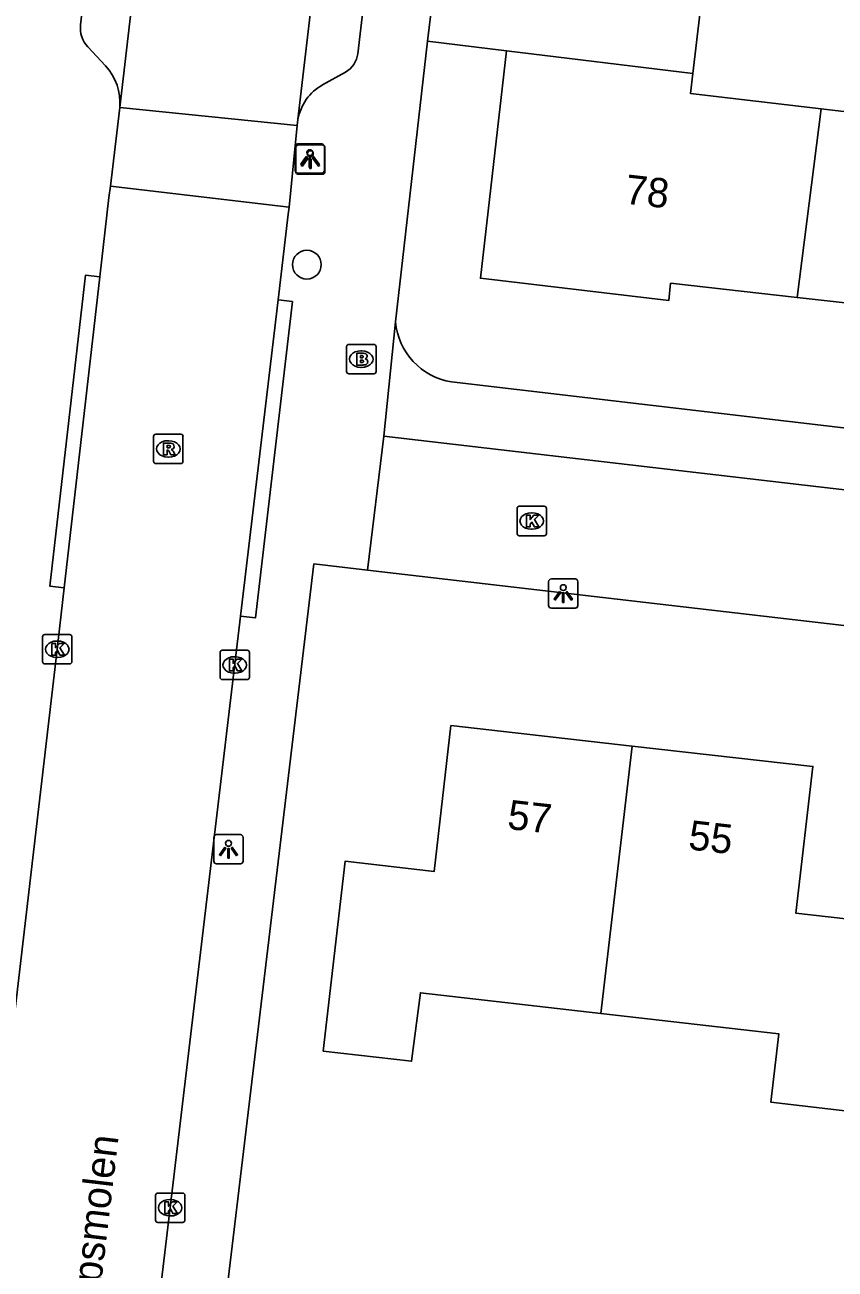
# Model space of a CAD drawing. Extents: x 161243 to 161752, y 384138 to 384885.
# Drawn here: x 161379.47 to 161407.09, y 384327.01 to 384369.39 of the extents above; entities that cross this region are included whole.
import ezdxf

# ---------------------------------------------------------------- set-up
doc = ezdxf.new("R2010")
doc.units = 0
for name, color, linetype in [('IMGEO_Boom', 7, 'Continuous'), ('IMGEO_Brandkraan', 7, 'Continuous'), ('IMGEO_Kolk', 7, 'Continuous'), ('IMGEO_Lichtpunt', 7, 'Continuous'), ('IMGEO_Openbare_ruimte_label', 7, 'Continuous'), ('IMGEO_Pand', 7, 'Continuous'), ('IMGEO_Pand_nummerreeks', 7, 'Continuous'), ('IMGEO_Rijbaan_lokaal_open', 7, 'Continuous'), ('IMGEO_Rioolput', 7, 'Continuous'), ('IMGEO_Voetpad_open', 7, 'Continuous')]:
    doc.layers.add(name, color=color, linetype=linetype)

msp = doc.modelspace()

# ---------------------------------------------------------------- linework, layer by layer
at = {"layer": 'IMGEO_Boom'}
msp.add_circle((161389.083, 384361.226), 0.489, dxfattribs=at)
at = {"layer": 'IMGEO_Brandkraan'}
for p, q in [((161390.438, 384357.582), (161390.438, 384358.434)), ((161390.513, 384358.508), (161391.365, 384358.508)), ((161390.926, 384358.288), (161390.951, 384358.288)), ((161391.439, 384358.434), (161391.439, 384357.582)), ((161391.365, 384357.508), (161390.513, 384357.508)), ((161390.949, 384357.728), (161390.924, 384357.728))]:
    msp.add_line(p, q, dxfattribs=at)
for points in [[(161390.438, 384357.582), (161390.438, 384358.434)], [(161390.513, 384358.508), (161391.365, 384358.508)], [(161390.786, 384358.208), (161390.786, 384357.808), (161390.999, 384357.808)], [(161391.017, 384358.208), (161390.786, 384358.208)], [(161391.439, 384358.434), (161391.439, 384357.582)], [(161390.965, 384358.127), (161390.911, 384358.127), (161390.911, 384358.051)], [(161390.911, 384358.051), (161390.964, 384358.051)], [(161390.973, 384357.975), (161390.911, 384357.975), (161390.911, 384357.894)], [(161390.911, 384357.894), (161390.973, 384357.894)], [(161391.365, 384357.508), (161390.513, 384357.508)]]:
    msp.add_lwpolyline(points, dxfattribs=at)
for centre, radius, start, end in [((161390.515, 384358.432), 0.0765, 91.552, 178.448), ((161390.515, 384358.432), 0.0765, 91.552, 178.448), ((161391.021, 384358.063), 0.145, 59.4692, 91.5367), ((161391.363, 384358.432), 0.0765, 1.552, 88.448), ((161391.363, 384358.432), 0.0765, 1.552, 88.448), ((161390.966, 384358.089), 0.0379, 267.8285, 90.9355), ((161390.974, 384357.934), 0.0404, 269.8759, 90.5077), ((161391.005, 384358.059), 0.251, 268.6676, 293.5347), ((161391.046, 384358.11), 0.0922, 285.5137, 58.1501), ((161391.051, 384357.918), 0.105, 301.3115, 78.989), ((161390.515, 384357.584), 0.0765, 181.552, 268.448), ((161390.515, 384357.584), 0.0765, 181.552, 268.448), ((161391.363, 384357.584), 0.0765, 271.552, 358.448), ((161391.363, 384357.584), 0.0765, 271.552, 358.448)]:
    msp.add_arc(centre, radius, start, end, dxfattribs=at)
for centre, major_axis, ratio, start_param, end_param in [((161390.925, 384358.008), (-0.387, 0.002), 0.722429, 4.712389, 7.853982), ((161390.95, 384358.008), (-0.39, 0.002), 0.717154, 1.570796, 4.712389)]:
    msp.add_ellipse(centre, major_axis=major_axis, ratio=ratio, start_param=start_param, end_param=end_param, dxfattribs=at)
at = {"layer": 'IMGEO_Kolk'}
for p, q in [((161396.245, 384352.069), (161396.245, 384352.921)), ((161396.32, 384352.995), (161397.172, 384352.995)), ((161396.733, 384352.775), (161396.758, 384352.775)), ((161397.246, 384352.921), (161397.246, 384352.069)), ((161397.172, 384351.995), (161396.32, 384351.995)), ((161396.756, 384352.215), (161396.731, 384352.215)), ((161380.075, 384347.701), (161380.075, 384348.553)), ((161380.15, 384348.627), (161381.002, 384348.627)), ((161381.076, 384348.553), (161381.076, 384347.701)), ((161380.563, 384348.407), (161380.588, 384348.407)), ((161386.198, 384348.092), (161387.05, 384348.092)), ((161381.002, 384347.627), (161380.15, 384347.627)), ((161380.586, 384347.847), (161380.561, 384347.847)), ((161386.123, 384347.166), (161386.123, 384348.018)), ((161386.611, 384347.872), (161386.636, 384347.872)), ((161387.124, 384348.018), (161387.124, 384347.166)), ((161386.634, 384347.312), (161386.609, 384347.312)), ((161387.05, 384347.092), (161386.198, 384347.092)), ((161383.924, 384328.677), (161383.924, 384329.529)), ((161383.999, 384329.603), (161384.851, 384329.603)), ((161384.925, 384329.529), (161384.925, 384328.677)), ((161384.412, 384329.383), (161384.437, 384329.383)), ((161384.851, 384328.603), (161383.999, 384328.603)), ((161384.435, 384328.823), (161384.41, 384328.823))]:
    msp.add_line(p, q, dxfattribs=at)
for points in [[(161396.245, 384352.069), (161396.245, 384352.921)], [(161396.32, 384352.995), (161397.172, 384352.995)], [(161397.246, 384352.921), (161397.246, 384352.069)], [(161396.566, 384352.695), (161396.689, 384352.695), (161396.689, 384352.544), (161396.819, 384352.695), (161396.983, 384352.695), (161396.837, 384352.544), (161396.99, 384352.295), (161396.838, 384352.295), (161396.753, 384352.459), (161396.689, 384352.392), (161396.689, 384352.295), (161396.566, 384352.295), (161396.566, 384352.695)], [(161397.172, 384351.995), (161396.32, 384351.995)], [(161380.075, 384347.701), (161380.075, 384348.553)], [(161380.15, 384348.627), (161381.002, 384348.627)], [(161381.076, 384348.553), (161381.076, 384347.701)], [(161380.396, 384348.327), (161380.519, 384348.327), (161380.519, 384348.176), (161380.649, 384348.327), (161380.813, 384348.327), (161380.667, 384348.176), (161380.82, 384347.927), (161380.668, 384347.927), (161380.583, 384348.091), (161380.519, 384348.024), (161380.519, 384347.927), (161380.396, 384347.927), (161380.396, 384348.327)], [(161386.198, 384348.092), (161387.05, 384348.092)], [(161381.002, 384347.627), (161380.15, 384347.627)], [(161386.123, 384347.166), (161386.123, 384348.018)], [(161386.444, 384347.792), (161386.567, 384347.792), (161386.567, 384347.641), (161386.697, 384347.792), (161386.861, 384347.792), (161386.715, 384347.641), (161386.868, 384347.392), (161386.716, 384347.392), (161386.631, 384347.556), (161386.567, 384347.489), (161386.567, 384347.392), (161386.444, 384347.392), (161386.444, 384347.792)], [(161387.124, 384348.018), (161387.124, 384347.166)], [(161387.05, 384347.092), (161386.198, 384347.092)], [(161383.924, 384328.677), (161383.924, 384329.529)], [(161383.999, 384329.603), (161384.851, 384329.603)], [(161384.925, 384329.529), (161384.925, 384328.677)], [(161384.245, 384329.303), (161384.368, 384329.303), (161384.368, 384329.152), (161384.498, 384329.303), (161384.662, 384329.303), (161384.516, 384329.152), (161384.669, 384328.903), (161384.517, 384328.903), (161384.432, 384329.067), (161384.368, 384329), (161384.368, 384328.903), (161384.245, 384328.903), (161384.245, 384329.303)], [(161384.851, 384328.603), (161383.999, 384328.603)]]:
    msp.add_lwpolyline(points, dxfattribs=at)
for centre, start, end in [((161396.322, 384352.919), 91.552, 178.448), ((161396.322, 384352.919), 91.552, 178.448), ((161397.17, 384352.919), 1.552, 88.448), ((161397.17, 384352.919), 1.552, 88.448), ((161396.322, 384352.071), 181.552, 268.448), ((161396.322, 384352.071), 181.552, 268.448), ((161397.17, 384352.071), 271.552, 358.448), ((161397.17, 384352.071), 271.552, 358.448), ((161380.152, 384348.551), 91.552, 178.448), ((161380.152, 384348.551), 91.552, 178.448), ((161381, 384348.551), 1.552, 88.448), ((161381, 384348.551), 1.552, 88.448), ((161386.2, 384348.016), 91.552, 178.448), ((161386.2, 384348.016), 91.552, 178.448), ((161387.048, 384348.016), 1.552, 88.448), ((161387.048, 384348.016), 1.552, 88.448), ((161380.152, 384347.703), 181.552, 268.448), ((161380.152, 384347.703), 181.552, 268.448), ((161381, 384347.703), 271.552, 358.448), ((161381, 384347.703), 271.552, 358.448), ((161386.2, 384347.168), 181.552, 268.448), ((161386.2, 384347.168), 181.552, 268.448), ((161387.048, 384347.168), 271.552, 358.448), ((161387.048, 384347.168), 271.552, 358.448), ((161384.001, 384329.527), 91.552, 178.448), ((161384.001, 384329.527), 91.552, 178.448), ((161384.849, 384329.527), 1.552, 88.448), ((161384.849, 384329.527), 1.552, 88.448), ((161384.001, 384328.679), 181.552, 268.448), ((161384.001, 384328.679), 181.552, 268.448), ((161384.849, 384328.679), 271.552, 358.448), ((161384.849, 384328.679), 271.552, 358.448)]:
    msp.add_arc(centre, 0.0765, start, end, dxfattribs=at)
for centre, major_axis, ratio, start_param, end_param in [((161396.732, 384352.495), (-0.387, 0.002), 0.722429, 4.712389, 7.853982), ((161396.757, 384352.495), (-0.39, 0.002), 0.717154, 1.570796, 4.712389), ((161380.562, 384348.127), (-0.387, 0.002), 0.722429, 4.712389, 7.853982), ((161380.587, 384348.127), (-0.39, 0.002), 0.717154, 1.570796, 4.712389), ((161386.61, 384347.592), (-0.387, 0.002), 0.722429, 4.712389, 7.853982), ((161386.635, 384347.592), (-0.39, 0.002), 0.717154, 1.570796, 4.712389), ((161384.411, 384329.103), (-0.387, 0.002), 0.722429, 4.712389, 7.853982), ((161384.436, 384329.103), (-0.39, 0.002), 0.717154, 1.570796, 4.712389)]:
    msp.add_ellipse(centre, major_axis=major_axis, ratio=ratio, start_param=start_param, end_param=end_param, dxfattribs=at)
at = {"layer": 'IMGEO_Lichtpunt'}
for p, q in [((161388.686, 384365.243), (161388.686, 384364.436)), ((161388.686, 384365.243), (161388.686, 384364.436)), ((161388.703, 384365.208), (161388.703, 384364.401)), ((161388.703, 384365.208), (161388.703, 384364.401)), ((161389.588, 384365.338), (161388.78, 384365.338)), ((161389.588, 384365.338), (161388.78, 384365.338)), ((161389.605, 384365.303), (161388.797, 384365.303)), ((161389.605, 384365.303), (161388.797, 384365.303)), ((161389.682, 384364.436), (161389.682, 384365.243)), ((161389.682, 384364.436), (161389.682, 384365.243)), ((161389.699, 384364.401), (161389.699, 384365.208)), ((161389.699, 384364.401), (161389.699, 384365.208)), ((161388.78, 384364.342), (161389.588, 384364.342)), ((161388.78, 384364.342), (161389.588, 384364.342)), ((161388.797, 384364.307), (161389.605, 384364.307)), ((161388.797, 384364.307), (161389.605, 384364.307)), ((161397.322, 384350.427), (161397.322, 384349.62)), ((161397.322, 384350.427), (161397.322, 384349.62)), ((161398.224, 384350.522), (161397.416, 384350.522)), ((161398.224, 384350.522), (161397.416, 384350.522)), ((161398.318, 384349.62), (161398.318, 384350.427)), ((161398.318, 384349.62), (161398.318, 384350.427)), ((161397.416, 384349.526), (161398.224, 384349.526)), ((161397.416, 384349.526), (161398.224, 384349.526)), ((161385.913, 384341.718), (161385.913, 384340.911)), ((161385.913, 384341.718), (161385.913, 384340.911)), ((161386.815, 384341.813), (161386.007, 384341.813)), ((161386.815, 384341.813), (161386.007, 384341.813)), ((161386.909, 384340.911), (161386.909, 384341.718)), ((161386.909, 384340.911), (161386.909, 384341.718)), ((161386.007, 384340.817), (161386.815, 384340.817)), ((161386.007, 384340.817), (161386.815, 384340.817))]:
    msp.add_line(p, q, dxfattribs=at)
for points in [[(161389.06, 384364.907), (161389.099, 384364.879), (161388.911, 384364.617), (161388.873, 384364.644), (161389.06, 384364.907)], [(161389.077, 384364.872), (161389.116, 384364.844), (161388.928, 384364.582), (161388.89, 384364.609), (161389.077, 384364.872)], [(161389.162, 384364.859), (161389.209, 384364.859), (161389.209, 384364.537), (161389.162, 384364.537), (161389.162, 384364.859)], [(161389.179, 384364.824), (161389.226, 384364.824), (161389.226, 384364.502), (161389.179, 384364.502), (161389.179, 384364.824)], [(161389.272, 384364.879), (161389.31, 384364.906), (161389.497, 384364.644), (161389.458, 384364.616), (161389.272, 384364.879)], [(161389.289, 384364.844), (161389.327, 384364.871), (161389.514, 384364.609), (161389.475, 384364.581), (161389.289, 384364.844)], [(161397.696, 384350.091), (161397.735, 384350.063), (161397.547, 384349.801), (161397.509, 384349.828), (161397.696, 384350.091)], [(161397.798, 384350.043), (161397.845, 384350.043), (161397.845, 384349.721), (161397.798, 384349.721), (161397.798, 384350.043)], [(161397.908, 384350.063), (161397.946, 384350.09), (161398.133, 384349.828), (161398.094, 384349.8), (161397.908, 384350.063)], [(161386.287, 384341.382), (161386.326, 384341.354), (161386.138, 384341.092), (161386.1, 384341.119), (161386.287, 384341.382)], [(161386.389, 384341.334), (161386.436, 384341.334), (161386.436, 384341.012), (161386.389, 384341.012), (161386.389, 384341.334)], [(161386.499, 384341.354), (161386.537, 384341.381), (161386.724, 384341.119), (161386.685, 384341.091), (161386.499, 384341.354)]]:
    msp.add_lwpolyline(points, dxfattribs=at)
for centre in [(161389.185, 384365.041), (161389.202, 384365.006), (161397.821, 384350.225), (161386.412, 384341.516)]:
    msp.add_circle(centre, 0.0994, dxfattribs=at)
for centre, start, end in [((161388.78, 384365.243), 90, 180), ((161388.78, 384365.243), 90, 180), ((161388.797, 384365.208), 90, 180), ((161388.797, 384365.208), 90, 180), ((161389.588, 384365.243), 0, 90), ((161389.588, 384365.243), 0, 90), ((161389.605, 384365.208), 0, 90), ((161389.605, 384365.208), 0, 90), ((161388.78, 384364.436), 180, 270), ((161388.78, 384364.436), 180, 270), ((161388.797, 384364.401), 180, 270), ((161388.797, 384364.401), 180, 270), ((161389.588, 384364.436), 270, 0), ((161389.588, 384364.436), 270, 360), ((161389.605, 384364.401), 270, 0), ((161389.605, 384364.401), 270, 360), ((161397.416, 384350.427), 90, 180), ((161397.416, 384350.427), 90, 180), ((161398.224, 384350.427), 0, 90), ((161398.224, 384350.427), 0, 90), ((161397.416, 384349.62), 180, 270), ((161397.416, 384349.62), 180, 270), ((161398.224, 384349.62), 270, 0), ((161398.224, 384349.62), 270, 360), ((161386.007, 384341.718), 90, 180), ((161386.007, 384341.718), 90, 180), ((161386.815, 384341.718), 0, 90), ((161386.815, 384341.718), 0, 90), ((161386.007, 384340.911), 180, 270), ((161386.007, 384340.911), 180, 270), ((161386.815, 384340.911), 270, 0), ((161386.815, 384340.911), 270, 360)]:
    msp.add_arc(centre, 0.0946, start, end, dxfattribs=at)
at = {"layer": 'IMGEO_Pand'}
for points in [[(161393.932, 384374.913), (161393.196, 384368.833)], [(161402.961, 384373.893), (161402.239, 384367.742)], [(161395.885, 384368.511), (161393.196, 384368.833)], [(161405.794, 384360.109), (161401.479, 384360.594), (161401.416, 384360.003), (161394.995, 384360.762), (161395.885, 384368.511)], [(161395.885, 384368.511), (161402.239, 384367.742)], [(161402.239, 384367.742), (161402.158, 384367.051), (161406.611, 384366.529)], [(161406.611, 384366.529), (161410.938, 384366.021), (161411.046, 384366.935), (161417.35, 384366.195)], [(161405.794, 384360.109), (161406.611, 384366.529)], [(161416.255, 384357.153), (161410.075, 384357.9), (161410.278, 384359.606), (161405.794, 384360.109)], [(161399.102, 384335.722), (161392.952, 384336.426), (161392.653, 384334.095), (161389.643, 384334.439), (161390.383, 384340.906), (161393.423, 384340.557), (161393.992, 384345.524), (161400.164, 384344.828)], [(161399.102, 384335.722), (161400.164, 384344.828)], [(161400.164, 384344.828), (161406.328, 384344.133), (161405.748, 384339.132), (161408.659, 384338.804)], [(161407.906, 384332.349), (161404.896, 384332.694), (161405.163, 384335.028), (161399.102, 384335.722)]]:
    msp.add_lwpolyline(points, dxfattribs=at)
at = {"layer": 'IMGEO_Rijbaan_lokaal_open'}
for points in [[(161388.436, 384415.795), (161382.703, 384366.584)], [(161388.778, 384366.166), (161394.42, 384414.251)], [(161382.385, 384363.904), (161382.703, 384366.584)], [(161382.703, 384366.584), (161388.754, 384365.965)], [(161388.754, 384365.965), (161388.474, 384363.189)], [(161388.754, 384365.965), (161388.778, 384366.166)], [(161382.029, 384360.807), (161382.338, 384363.509), (161382.385, 384363.904)], [(161382.385, 384363.904), (161388.474, 384363.189)], [(161388.474, 384363.189), (161388.45, 384362.95), (161388.102, 384360.026)], [(161380.816, 384350.22), (161382.029, 384360.807)], [(161388.102, 384360.026), (161386.821, 384349.251)], [(161391.147, 384350.82), (161391.7, 384355.381)], [(161391.7, 384355.381), (161436.178, 384350.21)], [(161435.648, 384345.655), (161391.147, 384350.82)], [(161375.412, 384304.063), (161380.553, 384347.92), (161380.816, 384350.22)], [(161386.821, 384349.251), (161380.767, 384298.362)]]:
    msp.add_lwpolyline(points, dxfattribs=at)
at = {"layer": 'IMGEO_Rioolput'}
for p, q in [((161383.86, 384354.524), (161383.86, 384355.376)), ((161383.935, 384355.45), (161384.787, 384355.45)), ((161384.861, 384355.376), (161384.861, 384354.524)), ((161384.348, 384355.23), (161384.373, 384355.23)), ((161384.787, 384354.45), (161383.935, 384354.45)), ((161384.371, 384354.67), (161384.346, 384354.67))]:
    msp.add_line(p, q, dxfattribs=at)
for points in [[(161383.86, 384354.524), (161383.86, 384355.376)], [(161383.935, 384355.45), (161384.787, 384355.45)], [(161384.861, 384355.376), (161384.861, 384354.524)], [(161384.449, 384355.148), (161384.197, 384355.15), (161384.197, 384354.75)], [(161384.197, 384354.75), (161384.321, 384354.75), (161384.321, 384354.912), (161384.332, 384354.912)], [(161384.375, 384355.069), (161384.321, 384355.069), (161384.321, 384354.988)], [(161384.321, 384354.988), (161384.373, 384354.988)], [(161384.379, 384354.883), (161384.45, 384354.75), (161384.59, 384354.75), (161384.525, 384354.876)], [(161384.787, 384354.45), (161383.935, 384354.45)]]:
    msp.add_lwpolyline(points, dxfattribs=at)
for centre, radius, start, end in [((161383.937, 384355.374), 0.0765, 91.552, 178.448), ((161383.937, 384355.374), 0.0765, 91.552, 178.448), ((161384.785, 384355.374), 0.0765, 1.552, 88.448), ((161384.785, 384355.374), 0.0765, 1.552, 88.448), ((161384.331, 384354.859), 0.0533, 26.0293, 88.6989), ((161384.357, 384355.177), 0.19, 274.7715, 282.9687), ((161384.381, 384354.973), 0.0964, 77.0061, 93.1865), ((161384.395, 384355.03), 0.0378, 276.6634, 79.6772), ((161384.448, 384355.038), 0.109, 350.3612, 89.416), ((161384.446, 384355.038), 0.112, 277.5842, 350.9817), ((161384.43, 384354.823), 0.108, 29.5134, 73.7905), ((161383.937, 384354.526), 0.0765, 181.552, 268.448), ((161383.937, 384354.526), 0.0765, 181.552, 268.448), ((161384.785, 384354.526), 0.0765, 271.552, 358.448), ((161384.785, 384354.526), 0.0765, 271.552, 358.448)]:
    msp.add_arc(centre, radius, start, end, dxfattribs=at)
for centre, major_axis, ratio, start_param, end_param in [((161384.347, 384354.95), (-0.387, 0.002), 0.722429, 4.712389, 7.853982), ((161384.372, 384354.95), (-0.39, 0.002), 0.717154, 1.570796, 4.712389)]:
    msp.add_ellipse(centre, major_axis=major_axis, ratio=ratio, start_param=start_param, end_param=end_param, dxfattribs=at)
at = {"layer": 'IMGEO_Voetpad_open'}
for points in [[(161381.37, 384369.393), (161386.534, 384413.313)], [(161390.818, 384368.412), (161395.846, 384411.348)], [(161393.196, 384368.833), (161392.099, 384359.279)], [(161382.218, 384368.003), (161381.617, 384368.644)], [(161389.617, 384367.348), (161390.398, 384367.783)], [(161380.816, 384350.22), (161380.32, 384350.276), (161381.533, 384360.863), (161382.029, 384360.807)], [(161388.102, 384360.026), (161388.591, 384359.969), (161387.33, 384349.191), (161386.821, 384349.251)], [(161392.099, 384359.279), (161391.7, 384355.381)], [(161490.429, 384345.932), (161394.009, 384357.23)], [(161391.147, 384350.82), (161389.324, 384351.032), (161386.343, 384326.184)]]:
    msp.add_lwpolyline(points, dxfattribs=at)
for centre, radius, start, end in [((161382.301, 384369.285), 0.938, 173.3787, 223.1236), ((161389.988, 384368.512), 0.836, 299.3749, 353.1609), ((161380.874, 384366.751), 1.837, 354.7764, 42.9634), ((161390.438, 384365.877), 1.685, 119.1538, 170.1109), ((161394.378, 384359.489), 2.288, 185.2536, 260.7248)]:
    msp.add_arc(centre, radius, start, end, dxfattribs=at)

# ---------------------------------------------------------------- texts
at = {"layer": 'IMGEO_Openbare_ruimte_label'}
msp.add_text('Bisschopsmolen', height=1, rotation=83.2232, dxfattribs=at).set_placement((161381.519, 384321.859))
at = {"layer": 'IMGEO_Pand_nummerreeks'}
for s, rotation, p in [('78', 353.5908, (161399.89, 384363.308)), ('57', 353.5665, (161395.887, 384342.01)), ('55', 353.5665, (161402.055, 384341.314))]:
    msp.add_text(s, height=1, rotation=rotation, dxfattribs=at).set_placement(p)

doc.saveas('drawing.dxf')
